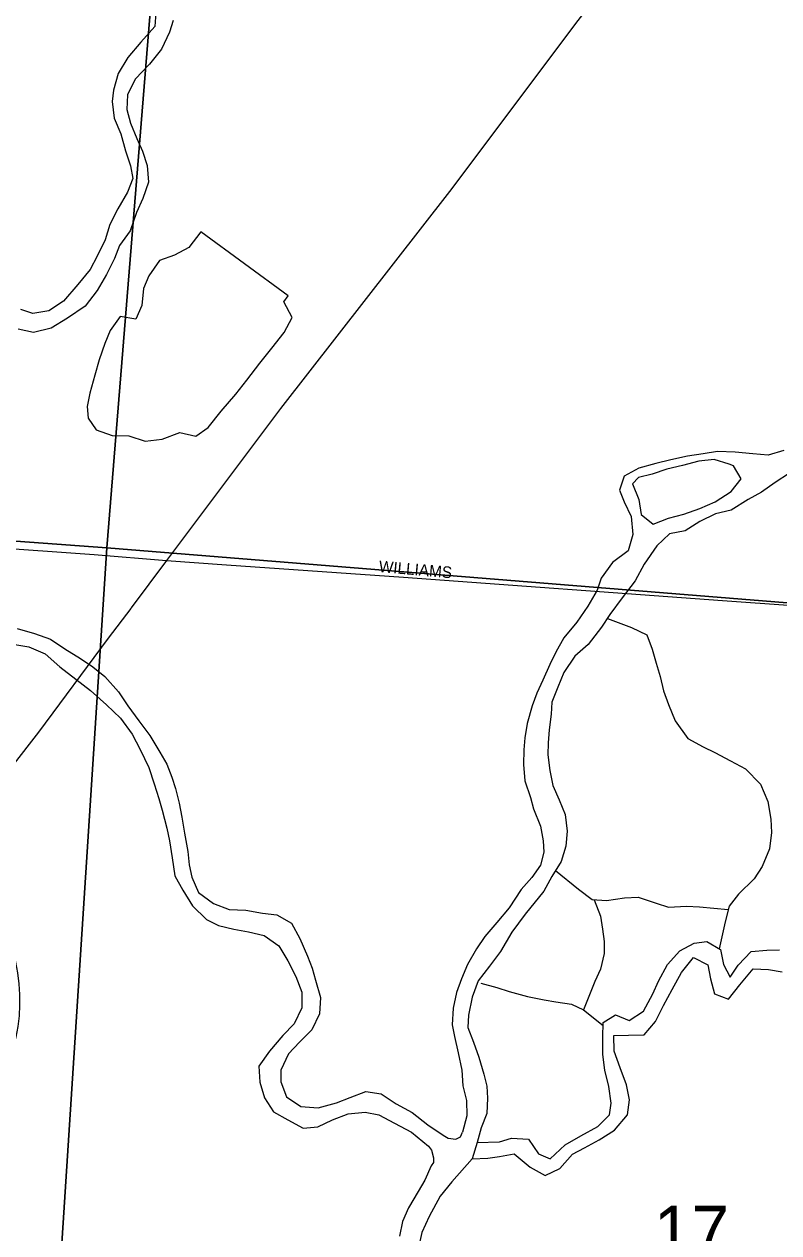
# Model space of a CAD drawing. Extents: x 0 to 34, y 0 to 22.
# Drawn here: x 4.973 to 5.595, y 15.628 to 16.625 of the extents above; entities that cross this region are included whole.
import ezdxf

# ---------------------------------------------------------------- set-up
doc = ezdxf.new("R2010")
doc.units = 0
for name, color, linetype in [('GM_X_City_Street', 7, 'Continuous'), ('GM_X_City_Street_Text', 7, 'Continuous'), ('GM_X_County_Road', 7, 'Continuous'), ('GM_X_Interstate_Route', 7, 'Continuous'), ('GM_X_Interstate_Shield', 7, 'Continuous'), ('GM_X_Major_River', 7, 'Continuous'), ('GM_X_Minor_Lake', 7, 'Continuous'), ('GM_X_Minor_River', 7, 'Continuous'), ('GM_X_Section', 7, 'Continuous'), ('GM_X_Section_Text', 7, 'Continuous')]:
    doc.layers.add(name, color=color, linetype=linetype)

msp = doc.modelspace()

# ---------------------------------------------------------------- linework, layer by layer
at = {"layer": 'GM_X_City_Street'}
msp.add_lwpolyline([(5.13963, 16.17877), (5.28533, 16.16855), (5.54857, 16.14934), (5.71868, 16.13728), (5.75367, 16.13486), (5.78413, 16.13225)], dxfattribs=at)
at = {"layer": 'GM_X_County_Road'}
msp.add_lwpolyline([(4.34683, 16.2372), (4.5216, 16.22516), (4.76374, 16.20621), (5.03029, 16.18729), (5.09005, 16.18225), (5.13962, 16.17877), (5.13963, 16.17877)], dxfattribs=at)
at = {"layer": 'GM_X_Interstate_Route'}
for points in [[(5.60641, 16.85998), (5.56117, 16.79829), (5.42915, 16.62769), (5.32352, 16.48666), (5.18413, 16.30773), (5.09005, 16.18225)], [(5.09005, 16.18225), (5.06079, 16.14318), (5.06054, 16.14284)], [(5.06054, 16.14284), (5.04206, 16.11817), (4.98455, 16.04083), (4.84173, 15.85735), (4.74385, 15.73112), (4.64558, 15.59842), (4.62857, 15.576), (4.62487, 15.57112)]]:
    msp.add_lwpolyline(points, dxfattribs=at)
at = {"layer": 'GM_X_Interstate_Shield'}
msp.add_ellipse((4.74731, 15.81916), major_axis=(0.22195, 0), ratio=0.8, start_param=4.913747, end_param=6.513751, dxfattribs=at)
at = {"layer": 'GM_X_Major_River'}
for points in [[(5.09563, 16.62756), (5.0926, 16.61807), (5.08578, 16.60404), (5.07593, 16.59152), (5.06419, 16.57938), (5.05776, 16.56648), (5.05738, 16.55434), (5.0604, 16.54297), (5.0657, 16.53046), (5.07024, 16.51984), (5.07402, 16.50809), (5.07516, 16.49444), (5.07061, 16.48078), (5.06531, 16.4694), (5.06, 16.45423), (5.05129, 16.44209), (5.04713, 16.43147), (5.04069, 16.41819), (5.03273, 16.40491), (5.02288, 16.39201), (5.00849, 16.38215), (4.99486, 16.3738), (4.98047, 16.37038), (4.9676, 16.37302)], [(5.08124, 16.63437), (5.08048, 16.62262), (5.06874, 16.60972), (5.05814, 16.5972), (5.05018, 16.58392), (5.0464, 16.57027), (5.04526, 16.56078), (5.04677, 16.54713), (5.05245, 16.53424), (5.05623, 16.52021), (5.06039, 16.5077), (5.06228, 16.49746), (5.05774, 16.48608), (5.04978, 16.47243), (5.04334, 16.45953), (5.03955, 16.44663), (5.03274, 16.43336), (5.02706, 16.42235), (5.01683, 16.40984), (5.00509, 16.39618), (4.99297, 16.3882), (4.97972, 16.38592), (4.96987, 16.38933)], [(5.59915, 16.27289), (5.58627, 16.26909), (5.5734, 16.27022), (5.55901, 16.27173), (5.54425, 16.2721), (5.53251, 16.27019), (5.51963, 16.26829), (5.506, 16.26525), (5.49351, 16.26221), (5.4795, 16.25841), (5.46738, 16.25195), (5.46359, 16.2402), (5.46738, 16.23072), (5.47305, 16.21859), (5.47456, 16.2038), (5.47077, 16.19014), (5.4579, 16.18065), (5.44843, 16.16775), (5.44502, 16.15789), (5.43745, 16.14462), (5.42835, 16.13134), (5.41775, 16.11844), (5.41093, 16.10668), (5.40601, 16.09644), (5.40033, 16.08354), (5.3954, 16.07292), (5.39161, 16.0623), (5.38745, 16.04789), (5.38555, 16.03613), (5.38479, 16.02627), (5.38441, 16.01413), (5.38554, 16.00048), (5.39008, 15.98683), (5.39273, 15.97735), (5.39841, 15.96332), (5.40068, 15.95119), (5.40105, 15.94171), (5.3984, 15.93109), (5.3912, 15.92085), (5.38249, 15.91098), (5.37265, 15.89581), (5.36242, 15.88367), (5.35257, 15.87228), (5.34576, 15.86204), (5.33818, 15.84914), (5.33326, 15.83739), (5.32909, 15.82601), (5.32644, 15.81311), (5.32568, 15.79946), (5.32757, 15.7896), (5.33059, 15.77633), (5.33362, 15.76192), (5.33437, 15.74903), (5.3374, 15.73689), (5.33778, 15.72438), (5.33399, 15.71073)], [(5.5575, 16.26035), (5.55409, 16.26186), (5.54159, 16.26565), (5.5291, 16.26412), (5.51547, 16.2607), (5.50259, 16.25766), (5.49048, 16.25348), (5.47912, 16.25082), (5.47419, 16.24551)], [(5.47419, 16.24551), (5.47949, 16.23262), (5.48138, 16.22011), (5.49122, 16.21215), (5.5041, 16.21709), (5.51659, 16.22051), (5.52985, 16.22506), (5.54234, 16.23076), (5.5556, 16.23911), (5.56393, 16.24973), (5.5575, 16.26035)], [(5.60369, 16.25431), (5.59195, 16.24672), (5.58059, 16.23874), (5.56961, 16.23267), (5.55559, 16.22394), (5.54272, 16.2209), (5.52985, 16.21445), (5.51773, 16.20685), (5.50485, 16.20419), (5.49425, 16.19433), (5.48402, 16.17915), (5.47645, 16.1655), (5.46584, 16.15146), (5.45562, 16.1378), (5.4488, 16.12718), (5.43782, 16.11314), (5.42683, 16.10327), (5.41774, 16.09), (5.41282, 16.07786), (5.40789, 16.06534), (5.40713, 16.05548), (5.40562, 16.04259), (5.40486, 16.03197), (5.40448, 16.02211), (5.40599, 16.00921), (5.40864, 15.9967), (5.41394, 15.98495), (5.41886, 15.97282), (5.42037, 15.95917), (5.41923, 15.94665), (5.41544, 15.93413), (5.40786, 15.92162), (5.40105, 15.90948), (5.3859, 15.89051), (5.37491, 15.87571), (5.36545, 15.85978), (5.35636, 15.84764), (5.34689, 15.8355), (5.34196, 15.82222), (5.33893, 15.80743), (5.33855, 15.79719), (5.34309, 15.78506)], [(4.96679, 16.12615), (4.98118, 16.12198), (4.99443, 16.11744), (5.00617, 16.10948), (5.01904, 16.10153), (5.02926, 16.0947)], [(4.96338, 16.11325), (4.97664, 16.11098), (4.98988, 16.1053), (5.002, 16.09469), (5.01525, 16.08446), (5.02736, 16.07499), (5.04061, 16.06324), (5.05197, 16.05224), (5.06181, 16.03898), (5.06825, 16.02647)], [(5.02926, 16.0947), (5.03911, 16.08675), (5.05046, 16.07386), (5.05803, 16.06249), (5.06712, 16.04998), (5.0762, 16.03785), (5.08453, 16.0242), (5.09021, 16.01435), (5.09437, 16.00373), (5.0974, 15.99425), (5.10042, 15.98212), (5.10269, 15.97074), (5.10496, 15.95747), (5.10761, 15.9423), (5.10874, 15.93131), (5.11101, 15.92107), (5.11631, 15.90856), (5.1288, 15.89946), (5.14168, 15.89454), (5.15531, 15.89379), (5.16932, 15.89152), (5.18105, 15.89001), (5.19317, 15.88319), (5.19998, 15.87068), (5.20642, 15.85589), (5.2102, 15.84604), (5.21285, 15.83618), (5.21701, 15.82177), (5.21625, 15.8085), (5.20981, 15.79522), (5.19959, 15.78498), (5.1905, 15.77549), (5.18444, 15.76184), (5.18443, 15.75235), (5.18898, 15.73984), (5.20071, 15.73188), (5.2151, 15.73076), (5.23025, 15.73494), (5.24161, 15.73949), (5.25448, 15.74443), (5.26698, 15.74254), (5.27947, 15.7342), (5.29272, 15.72701), (5.30559, 15.71677), (5.31809, 15.70844)], [(5.06825, 16.02647), (5.07544, 16.01168), (5.07998, 15.99803), (5.08377, 15.9859), (5.08641, 15.97642), (5.0902, 15.96163), (5.09247, 15.95102), (5.09473, 15.93699), (5.097, 15.9222), (5.10344, 15.91044), (5.11139, 15.89756), (5.12312, 15.88618), (5.13297, 15.88126), (5.14546, 15.87824), (5.15758, 15.87597), (5.17045, 15.87294), (5.18256, 15.8646), (5.19013, 15.85209), (5.19657, 15.8392), (5.20149, 15.82631), (5.20149, 15.81342), (5.19542, 15.80014), (5.18596, 15.79066), (5.17497, 15.77776), (5.16626, 15.76524), (5.16702, 15.75196), (5.1708, 15.73907), (5.17837, 15.7277), (5.19011, 15.72088), (5.2026, 15.71406), (5.21472, 15.71521), (5.22684, 15.7209), (5.23971, 15.72584), (5.25372, 15.72736), (5.26508, 15.7251), (5.27795, 15.71828), (5.29196, 15.7107), (5.30597, 15.69933)], [(5.34309, 15.78506), (5.34763, 15.77255), (5.35179, 15.75852), (5.35406, 15.74866), (5.35482, 15.7388), (5.35406, 15.72628), (5.34951, 15.71453), (5.3461, 15.70239)], [(5.31809, 15.70844), (5.3223, 15.70589), (5.32865, 15.70492), (5.33232, 15.70687), (5.33399, 15.71073)], [(5.3461, 15.70239), (5.34216, 15.68872)], [(5.30597, 15.69933), (5.30862, 15.69588), (5.31009, 15.68977), (5.31009, 15.68586), (5.30823, 15.68303)], [(5.30823, 15.68303), (5.30293, 15.67127), (5.29763, 15.66178), (5.28967, 15.64851), (5.28475, 15.63713), (5.2821, 15.62499)], [(5.34216, 15.68872), (5.32527, 15.66976), (5.3158, 15.658), (5.30671, 15.64131), (5.30065, 15.62804), (5.29838, 15.61817)]]:
    msp.add_lwpolyline(points, dxfattribs=at)
at = {"layer": 'GM_X_Minor_Lake'}
for points in [[(5.11846, 16.45324), (5.10849, 16.44042), (5.0967, 16.43406), (5.08416, 16.42961), (5.07533, 16.41716), (5.07107, 16.40657), (5.0698, 16.39254), (5.06477, 16.3812), (5.05192, 16.38358), (5.04348, 16.37189), (5.03921, 16.3613), (5.03454, 16.34767), (5.03101, 16.33518), (5.0267, 16.32042), (5.02471, 16.30943), (5.02537, 16.29956), (5.03209, 16.29002), (5.0453, 16.28536), (5.05893, 16.28525), (5.07252, 16.28058), (5.08654, 16.28237), (5.10099, 16.28794), (5.11421, 16.2848), (5.1245, 16.29192), (5.13523, 16.3055), (5.1471, 16.31944), (5.1563, 16.33113), (5.16703, 16.34508), (5.177, 16.35752), (5.18696, 16.37034), (5.19352, 16.38281), (5.18683, 16.39576)], [(5.18683, 16.39576), (5.19028, 16.40067), (5.11846, 16.45324)]]:
    msp.add_lwpolyline(points, dxfattribs=at)
at = {"layer": 'GM_X_Minor_River'}
for points in [[(5.45355, 16.13459), (5.47355, 16.12705), (5.48598, 16.12088), (5.49041, 16.10908), (5.49371, 16.09767), (5.49701, 16.08664), (5.49993, 16.07486), (5.50399, 16.06344), (5.50954, 16.05011), (5.52, 16.03561), (5.53243, 16.02868), (5.54223, 16.02404), (5.55504, 16.01711), (5.56747, 16.01056), (5.57985, 15.99794), (5.58577, 15.98347), (5.58828, 15.96903), (5.58893, 15.95802), (5.58729, 15.94437), (5.58109, 15.93), (5.57456, 15.91981), (5.56157, 15.90702), (5.5539, 15.89721), (5.55075, 15.88434), (5.54588, 15.86211)], [(5.41083, 15.92651), (5.42984, 15.91113), (5.44112, 15.90268), (5.45285, 15.90183), (5.46764, 15.90399), (5.479, 15.90465), (5.49372, 15.8996), (5.50391, 15.89648), (5.51869, 15.89712), (5.52966, 15.89665), (5.55321, 15.89441)], [(5.44271, 15.90257), (5.4478, 15.88897), (5.4496, 15.87833), (5.45101, 15.86808), (5.45092, 15.85821), (5.44777, 15.84534), (5.44313, 15.83513), (5.43382, 15.81168)], [(5.3461, 15.70239), (5.36463, 15.70296), (5.3745, 15.70592), (5.3885, 15.70504), (5.39672, 15.69283), (5.40652, 15.68896), (5.41875, 15.70024), (5.43169, 15.70773), (5.44578, 15.71558), (5.45533, 15.72499), (5.45656, 15.73484), (5.4548, 15.74852), (5.45152, 15.76182), (5.44975, 15.77474), (5.44988, 15.78916), (5.45, 15.8013), (5.46028, 15.80767), (5.4716, 15.80302), (5.48341, 15.81052), (5.49112, 15.82487), (5.49576, 15.83546), (5.50308, 15.84906), (5.51341, 15.86036), (5.52521, 15.86671), (5.53545, 15.86815), (5.54675, 15.8616), (5.54928, 15.84906), (5.55486, 15.83877), (5.56139, 15.84858), (5.5721, 15.85988), (5.58498, 15.86091), (5.59559, 15.86121)], [(5.34216, 15.68872), (5.35503, 15.68938), (5.36452, 15.69082), (5.37665, 15.69299), (5.3898, 15.68188), (5.40223, 15.67495), (5.4144, 15.68092), (5.42473, 15.6926), (5.43463, 15.69784), (5.44681, 15.70457), (5.45938, 15.71243), (5.4701, 15.72525), (5.47173, 15.73738), (5.4692, 15.74992), (5.46403, 15.764), (5.45924, 15.7777), (5.45899, 15.7906), (5.47111, 15.79088), (5.48398, 15.79116), (5.49317, 15.80209), (5.49973, 15.81531), (5.50705, 15.82853), (5.51476, 15.84251), (5.52472, 15.85495), (5.5364, 15.84879), (5.53856, 15.83738), (5.54185, 15.82484), (5.55355, 15.82057), (5.56275, 15.83226), (5.57385, 15.84545), (5.58634, 15.84497), (5.59768, 15.84298)], [(5.34921, 15.83362), (5.36243, 15.83009), (5.37263, 15.82697), (5.38773, 15.82268), (5.40133, 15.81991), (5.41116, 15.81831), (5.42402, 15.81631), (5.43382, 15.81168), (5.44998, 15.79876)], [(5.3461, 15.70239), (5.34216, 15.68872)]]:
    msp.add_lwpolyline(points, dxfattribs=at)
at = {"layer": 'GM_X_Section'}
for points in [[(4.17667, 17.28411), (5.12297, 17.2087), (5.04078, 16.19273), (4.10657, 16.26127), (4.1718, 17.21632)], [(5.12297, 17.2087), (6.14388, 17.13103), (6.07795, 16.10891), (5.04078, 16.19273)], [(4.10657, 16.26127), (5.04078, 16.19273), (4.97458, 15.16858), (4.03703, 15.24884), (4.10136, 16.20182)], [(5.04078, 16.19273), (6.07795, 16.10891), (6.00383, 15.08864), (4.97458, 15.16858)]]:
    msp.add_lwpolyline(points, close=True, dxfattribs=at)

# ---------------------------------------------------------------- texts
at = {"layer": 'GM_X_City_Street_Text'}
msp.add_text('WILLIAMS', height=0.00947, rotation=355.02985, dxfattribs=at).set_placement((5.26481, 16.17285))
at = {"layer": 'GM_X_Section_Text'}
msp.add_text('17', height=0.041856, rotation=0.00001, dxfattribs=at).set_placement((5.49173, 15.60832))

doc.saveas('drawing.dxf')
